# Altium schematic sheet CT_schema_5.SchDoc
size 430 x 414 mm
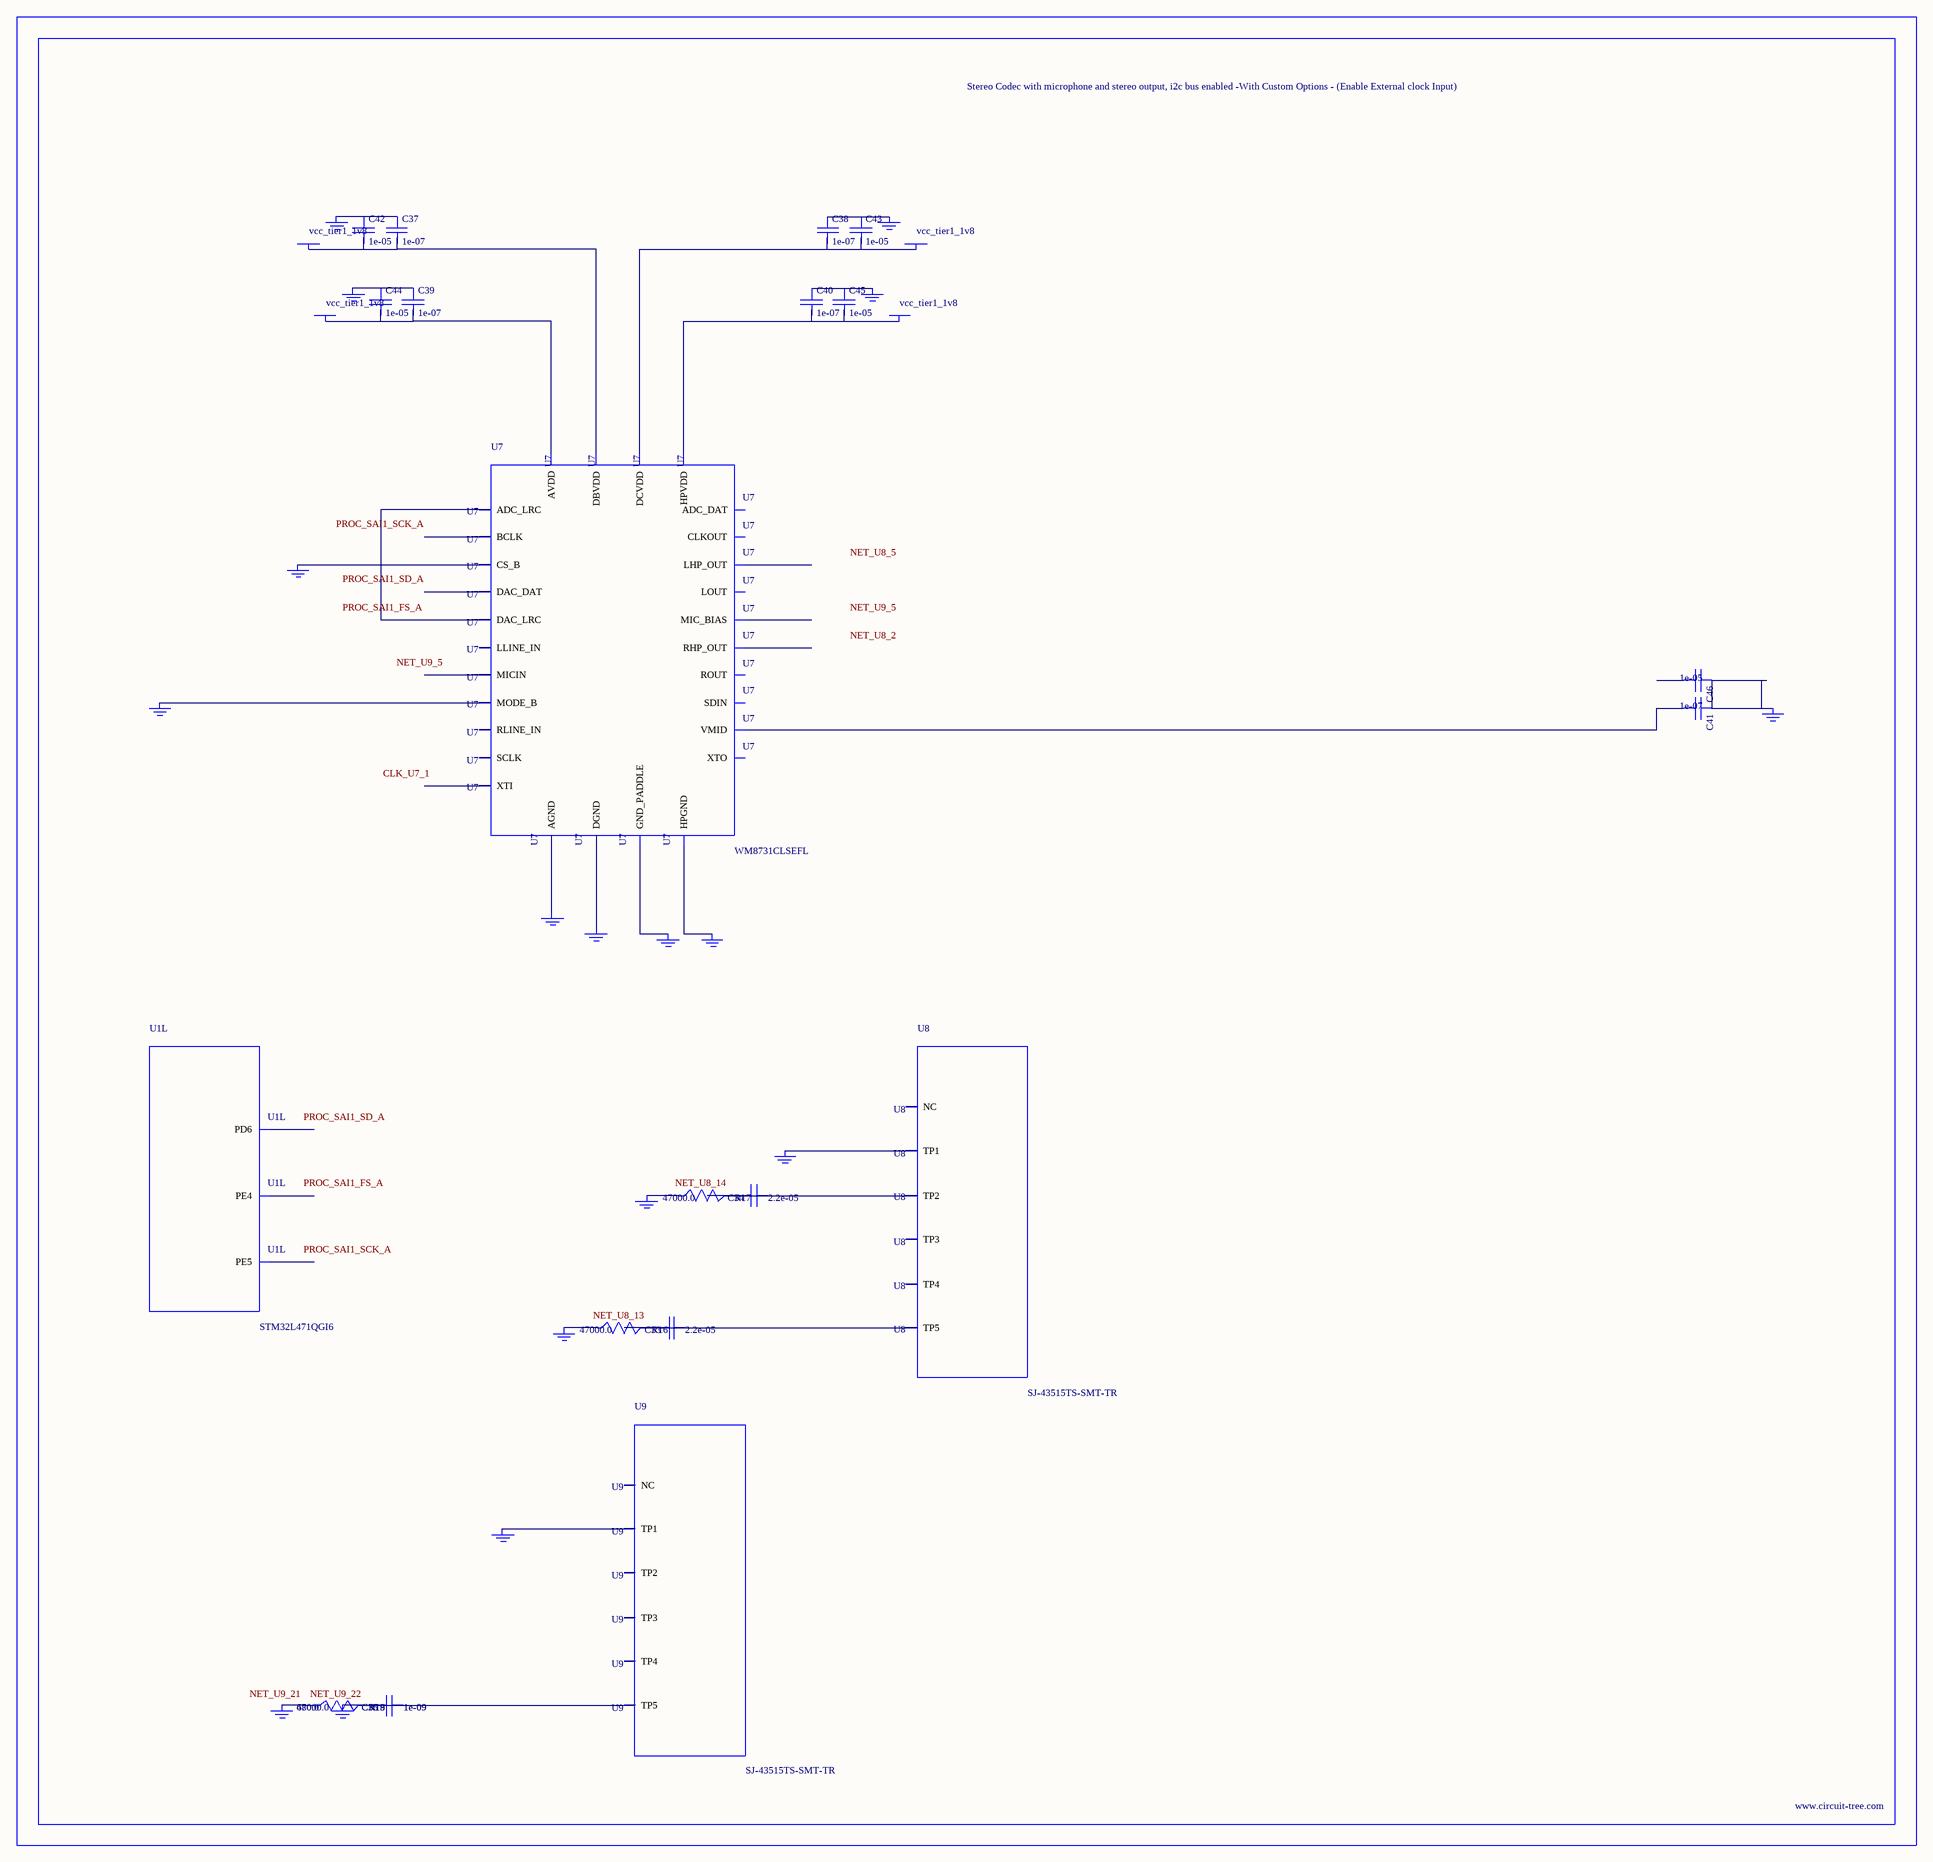
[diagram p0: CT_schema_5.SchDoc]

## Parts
BORDER4  (no value)
C33  2.2e-05  [C1210]
C34  2.2e-05  [C1210]
C35  1e-09  [C0402]
C36  1e-09  [C0402]
C37  1e-07  [C0402]
C38  1e-07  [C0402]
C39  1e-07  [C0402]
C40  1e-07  [C0402]
C41  1e-07  [C0402]
C42  1e-05  [C0805]
C43  1e-05  [C0805]
C44  1e-05  [C0805]
C45  1e-05  [C0805]
C46  1e-05  [C0805]
GND_INSTANCE_4_0  (no value)
GND_INSTANCE_4_1  (no value)
GND_INSTANCE_4_2  (no value)
GND_INSTANCE_4_3  (no value)
GND_INSTANCE_4_4  (no value)
GND_INSTANCE_4_5  (no value)
GND_INSTANCE_4_6  (no value)
GND_INSTANCE_4_7  (no value)
GND_INSTANCE_4_8  (no value)
GND_INSTANCE_4_9  (no value)
GND_INSTANCE_4_10  (no value)
GND_INSTANCE_4_11  (no value)
GND_INSTANCE_4_12  (no value)
GND_INSTANCE_4_13  (no value)
GND_INSTANCE_4_14  (no value)
GND_INSTANCE_4_15  (no value)
GND_INSTANCE_4_16  (no value)
POWER_INSTANCE_4_0  vcc_tier1_1v8
POWER_INSTANCE_4_1  vcc_tier1_1v8
POWER_INSTANCE_4_2  vcc_tier1_1v8
POWER_INSTANCE_4_3  vcc_tier1_1v8
R16  47000.0  [R0603]
R17  47000.0  [R0603]
R18  47000.0  [R0603]
R19  680.0  [R0603]
U1  STM32L471QGI6  [UFBGA132]  (part L of 12)
U7  WM8731CLSEFL  [QFN-28]
U8  SJ-43515TS-SMT-TR  [SJ-43515TS-SMT-TR]
U9  SJ-43515TS-SMT-TR  [SJ-43515TS-SMT-TR]

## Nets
NetC33_1: C33.1 C33.2 R16.2 U8.5(TP5)
NetC34_1: C34.1 C34.2 R17.2 U8.2(TP2)
NetC35_1: C35.1 C35.2 C36.1 C36.2 GND_INSTANCE_4_16.0(GND) R18.2 R19.2 U9.5(TP5)
NetC37_1: C37.1 C42.1 GND_INSTANCE_4_1.0(GND)
NetC37_2: C37.2 C42.2 POWER_INSTANCE_4_1.0(PWR) U7.5(DBVDD)
NetC38_1: C38.1 C43.1 GND_INSTANCE_4_0.0(GND)
NetC38_2: C38.2 C43.2 POWER_INSTANCE_4_0.0(PWR) U7.3(DCVDD)
NetC39_1: C39.1 C44.1 GND_INSTANCE_4_4.0(GND)
NetC39_2: C39.2 C44.2 POWER_INSTANCE_4_3.0(PWR) U7.18(AVDD)
NetC40_1: C40.1 C45.1 GND_INSTANCE_4_2.0(GND)
NetC40_2: C40.2 C45.2 POWER_INSTANCE_4_2.0(PWR) U7.12(HPVDD)
NetC41_1: C41.1 C46.1 GND_INSTANCE_4_5.0(GND)
NetC41_2: C41.2 U7.20(VMID)
NetGND_INSTANCE_4_3_0: GND_INSTANCE_4_3.0(GND) U7.15(HPGND)
NetGND_INSTANCE_4_6_0: GND_INSTANCE_4_6.0(GND) U7.25(MODE_B)
NetGND_INSTANCE_4_7_0: GND_INSTANCE_4_7.0(GND) U7.26(CS_B)
NetGND_INSTANCE_4_8_0: GND_INSTANCE_4_8.0(GND) U7.29(GND_PADDLE)
NetGND_INSTANCE_4_9_0: GND_INSTANCE_4_9.0(GND) U7.4(DGND)
NetGND_INSTANCE_4_10_0: GND_INSTANCE_4_10.0(GND) U7.19(AGND)
NetGND_INSTANCE_4_11_0: GND_INSTANCE_4_11.0(GND) U8.1(TP1)
NetGND_INSTANCE_4_12_0: GND_INSTANCE_4_12.0(GND) R17.1
NetGND_INSTANCE_4_13_0: GND_INSTANCE_4_13.0(GND) R16.1
NetGND_INSTANCE_4_14_0: GND_INSTANCE_4_14.0(GND) U9.1(TP1)
NetGND_INSTANCE_4_15_0: GND_INSTANCE_4_15.0(GND) R18.1 R19.1
NetU7_9: U7.9(DAC_LRC) U7.11(ADC_LRC)

Not connected (* = marked no-connect by the designer): C46 2; U1 B1(PE4) B6(PD6) C2(PE5); U7 1(XTI) 2(XTO) 6(CLKOUT) 7(BCLK) 8(DAC_DAT) 10(ADC_DAT) 13(LHP_OUT) 14(RHP_OUT) 16(LOUT) 17(ROUT) 21(MIC_BIAS) 22(MICIN) 23(RLINE_IN) 24(LLINE_IN) 27(SDIN) 28(SCLK); U8 3(TP3) 4(TP4) 6(NC); U9 2(TP2) 3(TP3) 4(TP4) 6(NC)

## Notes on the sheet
- Labels drawn without touching a wire or pin: CLK_U7_1, NET_U8_2, NET_U8_5, NET_U8_13, NET_U8_14, NET_U9_5, NET_U9_21, NET_U9_22, PROC_SAI1_FS_A, PROC_SAI1_SCK_A, PROC_SAI1_SD_A

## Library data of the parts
BORDER4 = BORDER_PAGE4
C33 C34 = C1210C224K5RACTU
C35 C36 = C0402C102K3RAC
C37-C41 = C0402C104K3RACTU
C42-C46 = C0805C106K8RACTU
GND_INSTANCE_4_0-GND_INSTANCE_4_16 = GND
POWER_INSTANCE_4_0-POWER_INSTANCE_4_3 = PWR
R16-R18 = RC0603JR-0747KL
R19 = RC0603JR-07680RL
